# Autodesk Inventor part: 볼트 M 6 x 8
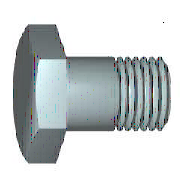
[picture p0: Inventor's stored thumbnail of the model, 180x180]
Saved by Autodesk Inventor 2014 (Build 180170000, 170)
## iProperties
Created: 2012-02
Part Number: 볼트 M 6 x 8
Material: 강철, 연강
Description: 6각 머리 볼트 및 6각 머리 나사
Document SubType Name: Modeling
Standard: KS B 1002
Designer: mduedu
Standards Organization: KS
Language: ko-KR
Size Designation: C  M 6 x 12
Categories: <MemberInstance><Categories><Category DisplayName="조임쇠" InternalName="e4da775c-781d-43d5-af7c-5136215cf5a6" Mnemonic="FSTN"><Category DisplayName="볼트" InternalN
Density: 1 g/cm^3
Appearance: Steel
IsCustomPart: 1
Author: mduedu
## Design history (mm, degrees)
sketch "스케치1"
  geometry: L1 (0, 3)-(8, 3); L2 (8, 3)-(8, 0); L3 (8, 0)-(0, 0); L4 (-2.4, 0)-(14.4, 0) reference; L5 (0, -0.6)-(0, 3.6) reference; L6 (0, 3)-(0, 0)
  constraints: 8 end point, 3 point on line, 1 collinear
  dimensions: "d2" = 6 diameter of L1 L3 (= GD); "d59" = 8 distance between parallel lines of L2 L5 (= NLG)
revolve "본체" sketch "스케치1" stored, may be unused: angle "d12" = 90 deg
sketch "스케치2"
  geometry: L1 (0, 5.774)-(5, 2.887); L2 (5, 2.887)-(5, -2.887); L3 (5, -2.887)-(0, -5.774); L4 (0, -5.774)-(-5, -2.887); L5 (-5, -2.887)-(-5, 2.887); L6 (-5, 2.887)-(0, 5.774); L7 (-7, 0)-(7, 0) reference; L8 (0, 8.083)-(0, -8.083) reference; 2 further points
  constraints: 12 end point, 2 midpoint, 1 coincident, 1 vertical, 11 other
  dimensions: "d11" = 10 distance between parallel lines of L5 L2 (= SW)
extrude "머리" join sketch "스케치2" distance "d3" = 4 (= KOH); taper "d4" = 0 deg
revolve "모따기1" stored, may be unused: angle "d21" = 90 deg
workplane "Work Plane1"
body "Solid1"
feature "스레드" dims "d15" = 9 (= GEL), "d16" = 0
chamfer "모따기2" distance "d6" = 0.61345 (= -0.5 x SPD + 0.5 x GD); stored, may be unused: second distance "d7" = 0.61355 (computed from GUL), angle "d55" = 45 deg
sketch "스케치4"
  geometry: L1 (-3.423, 6)-(-4, 5); L2 (-1.1, 0)-(-0.234, 0); L3 (-4.753, 0)-(0.519, 0) reference; L4 (-4, 6)-(-3.423, 6); L5 (-4, 5)-(-4, 6); L6 (0, 7.2)-(0, -1.2) reference
  constraints: 8 end point, 1 parallel, 1 perpendicular, 1 point on line
  dimensions: "d65" = 10 diameter of L1.end L2 (= SW); "d67" = 30 deg angle of L1 L5 (= ANG1); "d68" = 12 diameter of L4 L2 (= 1.2 x SW); "d69" = 4 distance between parallel lines of L5 L6 (= KOH)
other parameters: "NLG" = 8 [user parameter; used in 1 equation term], "GD" = 6 (= NND) [user parameter; used in 2 equation terms], "BDM" = 6 (= NND) [user parameter], "KOH" = 4 [user parameter; used in 2 equation terms], "GEL" = 9 [user parameter; used in 1 equation term], "SW" = 10 [user parameter; used in 5 equation terms], "SPD" = 4.7731 (= NND - 1.2269 x PTC) [user parameter; used in 1 equation term], "SD2" = 6 (= NND) [user parameter], "SD" = 0 [user parameter], "ANG1" = 30 deg [user parameter; used in 1 equation term], "GAL" = 0.61345 (= 0.61345 x PTC) [user parameter], "GUL" = 0.61345 (= 0.61345 x PTC) [user parameter; used in 1 equation term], "d8" = 0, "RR" = 0.25 [user parameter], "d58" = 0, "RR1" = 0.1 [user parameter], "GD1" = 4.7731 (= THREADDIA - 1.2269 x PTC) [user parameter], "THREADDIA" = 6 [user parameter; used in 1 equation term], "TOA" = 30 deg [user parameter], "PTC" = 1 [user parameter; used in 5 equation terms], "NND" = 6 [user parameter; used in 4 equation terms], "E0" = 11.55 (= 1.155 x SW) [user parameter]
